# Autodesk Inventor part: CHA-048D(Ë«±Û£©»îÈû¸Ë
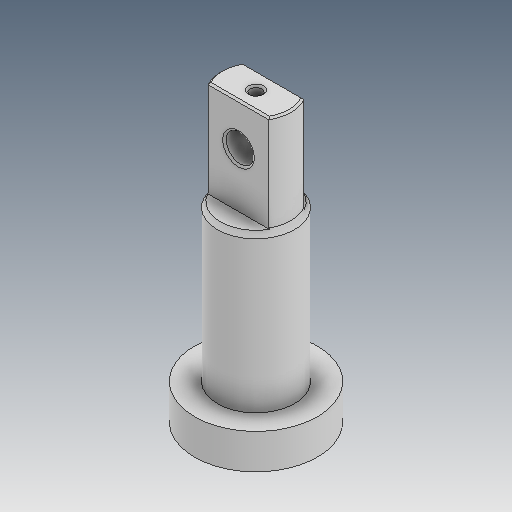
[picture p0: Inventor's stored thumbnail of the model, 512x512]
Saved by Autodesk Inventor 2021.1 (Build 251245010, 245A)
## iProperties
Created: 2019-12
Part Number: CHA-048D(Ë«±Û£©»îÈû¸Ë
Material: Ogólny
Document SubType Name: Modeling
Designer: user
Density: 1 g/cm^3
Appearance: Domyślna
Author: user
Revision Number: ÈÎºÎ
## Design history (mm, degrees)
feature "ÊäÈë1"
node "Bryła1"
